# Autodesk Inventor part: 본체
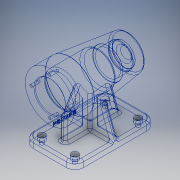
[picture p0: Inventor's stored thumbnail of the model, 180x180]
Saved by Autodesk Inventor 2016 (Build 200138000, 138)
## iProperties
Created: 2018-09
Part Number: 본체
Material: 알루미늄 6061
Document SubType Name: Modeling
Designer: 3sil_cad018
Density: 2.7 g/cm^3
Appearance: 알루미늄 - 평지
Mass: 731.898 g
Surface Area: 672.453 cm^2
Volume: 271.073 cm^3
Author: 3sil_cad018
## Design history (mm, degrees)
sketch "스케치1"
  geometry: L1 (0, 0)-(0, 34); L2 (0, 34)-(-28, 34); L3 (-28, 34)-(-112, 23.686); L4 (-112, 23.686)-(-112, 0); L5 (-112, 0)-(0, 0); A1 r 80 centre (-32, 0) between (-108.27, 24.144) and (-112, 0)
  constraints: 10 end point, 2 perpendicular, 2 point on circle, 2 point on line, 1 centre point, 1 parallel, 1 vertical
  dimensions: "d0" = 28 distance of L1.end L2.end; "d1" = 7 deg angle of L2 L3; "d2" = 112 distance between parallel lines of L1 L4; "d3" = 80 radius of A1; "d4" = 68 diameter of L2 L5
revolve "회전1" sketch "스케치1" stored, may be unused: angle "d5" = 90 deg
sketch "스케치2"
  geometry: L1 (0, 0)-(-15, 0); L2 (-15, 0)-(-15, 21); L3 (-15, 21)-(0, 21); L4 (0, 21)-(0, 0); L5 (-15, 0)-(-69, 0); L6 (-69, 0)-(-69, 24); L7 (-69, 24)-(-15, 24); L8 (-15, 24)-(-15, 0); L9 (-69, 0)-(-81, 0); L10 (-81, 0)-(-81, 21); L11 (-81, 21)-(-69, 21); L12 (-69, 21)-(-69, 0); L13 (-81, 0)-(-99, 0); L14 (-99, 0)-(-99, 17.5); L15 (-99, 17.5)-(-81, 17.5); L16 (-81, 17.5)-(-81, 0); L17 (-99, 0)-(-103, 0); L18 (-103, 0)-(-103, 16); L19 (-103, 16)-(-99, 16); L20 (-99, 16)-(-99, 0); L21 (-103, 0)-(-106, 0); L22 (-106, 0)-(-106, 10.5); L23 (-106, 10.5)-(-103, 10.5); L24 (-103, 10.5)-(-103, 0)
  constraints: 48 end point, 12 parallel, 6 horizontal, 6 perpendicular
  dimensions: "d6" = 15 distance of L2.end L3.end; "d7" = 54 distance of L6.end L7.end; "d8" = 12 distance of L10.end L11.end; "d9" = 18 distance of L14.end L15.end; "d10" = 4 distance of L18.end L19.end; "d11" = 3 distance of L22.end L23.end; "d12" = 42 diameter of L3 L1; "d13" = 48 diameter of L7 L5; "d14" = 42 diameter of L11 L5; "d15" = 35 diameter of L15 L9; "d16" = 32 diameter of L19 L17; "d17" = 21 diameter of L23 L21
revolve "회전2" sketch "스케치2" stored, may be unused: angle "d18" = 90 deg
sketch "스케치3" dims "d19" = 52
  geometry: 3 further points
  constraints: 1 coincident, 1 vertical alignment, 2 other
hole "구멍1" sketch "스케치3" at (0, 26) diameter "d20" = 3.242; stored, may be unused: countersink angle "d24" = 90 deg, drill point angle "d26" = 118 deg; dims "d21" = 8, "d22" = 4, "d23" = 2, "d25" = 11
node "작업 평면1"
sketch "스케치4"
  geometry: L1 (0, 35)-(112, 35); L2 (112, 35)-(112, -35); L3 (112, -35)-(0, -35); L4 (0, -35)-(0, 35); L5 (0, 35)-(112, -35); L6 (112, 35)-(0, -35); L7 (0, 34)-(0, -34) reference; 4 further points
  constraints: 12 end point, 4 midpoint, 2 parallel, 1 collinear, 1 horizontal, 1 horizontal alignment, 1 perpendicular
  dimensions: "d32" = 70 distance of L3.end L1.start; "d33" = 112 distance of L2.end L3.end
extrude "돌출1" join sketch "스케치4" distance "d34" = 10; taper "d35" = 0 deg
node "작업 평면2"
sketch "스케치7"
  geometry: L1 (0, -29.102)-(-8.297, -28.55); L2 (-8.297, -28.55)-(-19.33, -20.947); L3 (-19.33, -20.947)-(-35, -64); L4 (-35, -64)-(35, -64) reference; L5 (0, -64)-(0, -29.102); L6 (0, -64)-(-35, -64); L7 (0, -29.102)-(8.297, -28.55); L8 (8.297, -28.55)-(19.33, -20.947); L9 (19.33, -20.947)-(35, -64); L10 (35, -64)-(-35, -64); L11 (0, -64)-(35, -64); L12 (-35, -74)-(-35, -64) reference; 1 further point
  constraints: 20 end point, 5 symmetric about line, 2 point on line, 1 collinear, 1 midpoint, 1 perpendicular
  dimensions: "d41" = 20 deg angle of L3 L12
extrude "돌출2" join sketch "스케치7" stored distance "d42" = 8; taper "d43" = 0 deg
sketch "스케치8"
  geometry: L1 (-18, -33.939)-(-18, -64); L2 (-52, -64)-(0, -64) reference; L3 (0, -74)-(0, -64) reference; 1 further point
  constraints: 2 end point, 1 point on line, 1 vertical
  dimensions: "d44" = 18 distance between parallel lines of L1 L3
feature "리브1" sketch "스케치8" dims "d45" = 1, "d46" = 8, "d47" = 0, "d48" = 0, "d49" = 1, "d50" = 1
sketch "스케치9"
  geometry: L1 (-112, -64)-(-60, -64) reference; L2 (-94, -64)-(-84.115, -27.11); L3 (-108.27, -24.144)-(-60, -30.071) reference; L4 (-112, -74)-(-112, -64) reference; 1 further point
  constraints: 2 end point, 2 point on line
  dimensions: "d51" = 105 deg angle of L1 L2; "d52" = 18 distance from line of L2.start L4
feature "리브2" sketch "스케치9" dims "d53" = 1, "d54" = 8, "d55" = 0, "d56" = 0, "d57" = 1, "d58" = 1
fillet "모깎기1" dims "d59" = 12
sketch "스케치10"
  geometry: L1 (-18, -4)-(-52, -4) reference; L2 (-52, -4)-(-52, -35) reference; L3 (-52, -35)-(-60, -35) reference; L4 (-60, -35)-(-60, -4) reference; L5 (-60, -4)-(-94, -4) reference; L6 (-94, -4)-(-94, 4) reference; L7 (-94, 4)-(-60, 4) reference; L8 (-60, 4)-(-60, 35) reference; L9 (-100, 35)-(-60, 35) reference; L10 (-112, -23)-(-112, 23) reference; L11 (-60, -35)-(-100, -35) reference; L12 (-18, 4)-(-18, -4) reference; L13 (-52, 4)-(-18, 4) reference; L14 (-52, 35)-(-52, 4) reference; L15 (-60, 35)-(-52, 35) reference; L16 (-12, -35)-(-52, -35) reference; L17 (0, 23)-(0, -23) reference; L18 (-52, 35)-(-12, 35) reference; A1 r 12 centre (-100, 23) between (-100, 35) and (-112, 23) reference; A2 r 12 centre (-100, -23) between (-112, -23) and (-100, -35) reference; A3 r 12 centre (-12, -23) between (-12, -35) and (0, -23) reference; A4 r 12 centre (-12, 23) between (0, 23) and (-12, 35) reference; 1 further point
hole "구멍2" sketch "스케치10" at (-100, -23), (-100, 23), (-12, -23), (-12, 23) diameter "d60" = 5.5; stored, may be unused: countersink angle "d64" = 90 deg, drill point angle "d66" = 118 deg; dims "d61" = 8, "d62" = 9.5, "d63" = 5.4, "d65" = 11
fillet "모깎기2" dims "d67" = 3
fillet "모깎기3" dims "d68" = 3
chamfer "모따기1" distance "d69" = 1; stored, may be unused: second distance "d70" = 2, angle "d71" = 45 deg
fillet "모깎기4" dims "d72" = 0.3
sketch "스케치11"
  geometry: L1 (88, 0)-(0, 0) reference; L2 (100, 0)-(100, 7) reference; 2 further points
  constraints: 1 other
  dimensions: "d73" = 3 distance from line of L1 point (44, 3); "d74" = 56 distance from line of L2 point (44, 3)
feature "엠보싱1" sketch "스케치11" dims "d75" = 0.5, "d76" = 0
fillet "모깎기5" dims "d77" = 3
fillet "모깎기6" dims "d78" = 3
fillet "모깎기7" dims "d79" = 3
node "솔리드1"
pattern_circular "원형 패턴1" dims angle "d28" = 360 deg
node "절단 모서리 투영2"
other parameters: "d30" = -74, "d40" = -56
